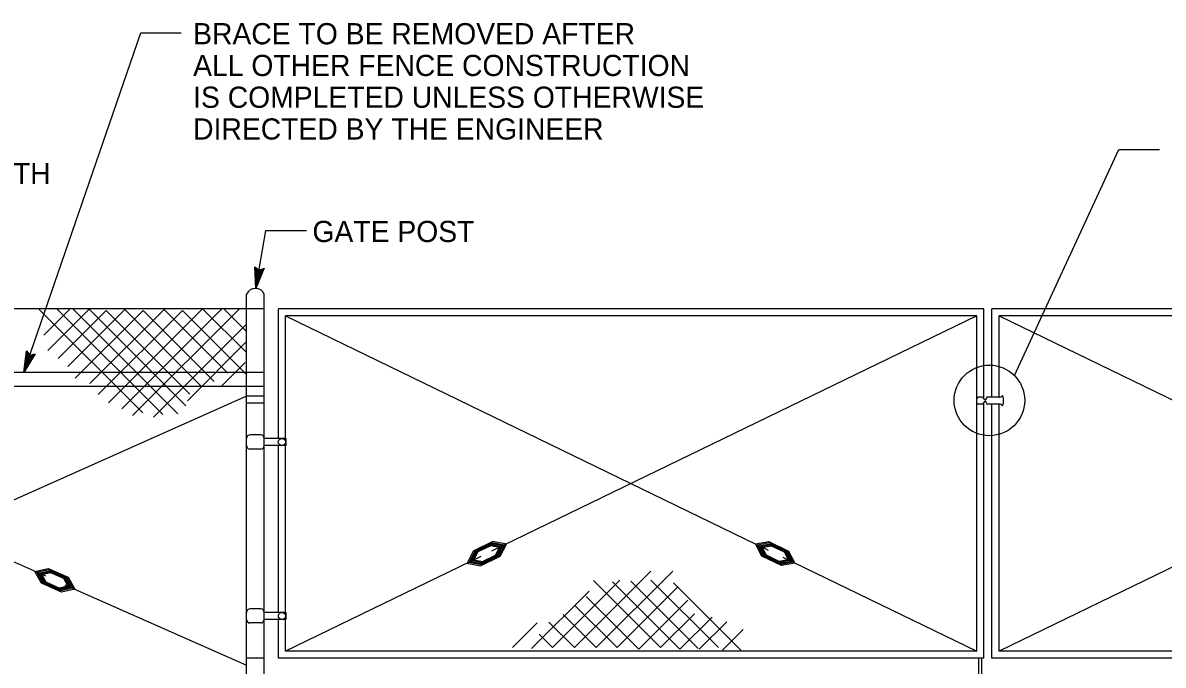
# Model space of a CAD drawing. Extents: x -121933 to -117742, y -103160 to -100084.
# Drawn here: x -121289.1 to -120965.9, y -102377.2 to -102195.2 of the extents above; entities that cross this region are included whole.
import ezdxf

# ---------------------------------------------------------------- set-up
doc = ezdxf.new("R2010")
doc.units = 0
for name, color, linetype in [('G-MARK', 7, 'Continuous'), ('Misc CnstDet(22)', 7, 'Continuous'), ('Nongeo Data(60)', 7, 'Continuous')]:
    doc.layers.add(name, color=color, linetype=linetype)

msp = doc.modelspace()

# ---------------------------------------------------------------- linework, layer by layer
at = {"layer": 'G-MARK'}
for p, q in [((-121255.73, -102197.99), (-121244.23, -102197.99)), ((-120978.4, -102231.09), (-120966.89, -102231.09)), ((-121220.22, -102254.04), (-121208.72, -102254.04)), ((-121223.06, -102270.41), (-121223.35, -102264.27)), ((-121223.35, -102264.27), (-121223.35, -102264.27)), ((-121223.35, -102264.27), (-121222.17, -102265.29)), ((-121220.72, -102264.73), (-121223.06, -102270.41)), ((-121222.83, -102269.04), (-121223.03, -102264.56)), ((-121221.1, -102264.88), (-121222.83, -102269.05)), ((-121222.59, -102267.69), (-121222.72, -102264.8)), ((-121221.5, -102265.05), (-121222.59, -102267.69)), ((-121222.35, -102266.33), (-121222.41, -102265.09)), ((-121221.87, -102265.16), (-121222.35, -102266.33)), ((-121222.17, -102265.29), (-121220.72, -102264.73)), ((-121220.72, -102264.73), (-121220.72, -102264.73)), ((-121223.06, -102270.41), (-121223.06, -102270.41)), ((-121288.84, -102294.24), (-121288.14, -102288.14)), ((-121285.62, -102289.01), (-121288.84, -102294.24)), ((-121288.39, -102292.93), (-121287.88, -102288.48)), ((-121286.02, -102289.09), (-121288.39, -102292.94)), ((-121288.14, -102288.14), (-121288.14, -102288.14)), ((-121288.14, -102288.14), (-121287.14, -102289.33)), ((-121287.94, -102291.63), (-121287.61, -102288.76)), ((-121286.44, -102289.2), (-121287.94, -102291.63)), ((-121287.49, -102290.33), (-121287.35, -102289.1)), ((-121286.83, -102289.25), (-121287.49, -102290.33)), ((-121287.14, -102289.33), (-121285.62, -102289.01)), ((-121285.62, -102289.01), (-121285.62, -102289.01)), ((-121288.84, -102294.24), (-121288.84, -102294.24))]:
    msp.add_line(p, q, dxfattribs=at)
for points in [[(-121288.84, -102294.24), (-121255.73, -102197.99), (-121255.73, -102197.99)], [(-121008.05, -102295.1), (-120978.4, -102231.09), (-120978.4, -102231.09)], [(-121223.06, -102270.41), (-121220.22, -102254.04)]]:
    msp.add_lwpolyline(points, dxfattribs=at)
msp.add_circle((-121015.12, -102302.17), 10, dxfattribs=at)
at = {"layer": 'Misc CnstDet(22)'}
msp.add_lwpolyline([(-121017.32, -102375.24), (-121017.32, -102390.2), (-121018.08, -102390.2), (-121018.08, -102375.24)], dxfattribs=at)
at = {"layer": 'Nongeo Data(60)'}
for p, q in [((-121225.7, -102358.97), (-121225.7, -102272.05)), ((-121220.7, -102358.97), (-121220.7, -102272.05)), ((-121220.7, -102276.24), (-121402.53, -102276.24)), ((-121255.16, -102305.72), (-121284.47, -102276.41)), ((-121283.17, -102283.65), (-121275.93, -102276.41)), ((-121282.1, -102288.04), (-121270.23, -102276.17)), ((-121249.46, -102306.2), (-121279.49, -102276.17)), ((-121279.13, -102290.29), (-121265.48, -102276.65)), ((-121276.4, -102292.55), (-121260.26, -102276.41)), ((-121245.19, -102305.96), (-121274.98, -102276.17)), ((-121274.27, -102295.87), (-121255.04, -102276.65)), ((-121242.94, -102303.7), (-121270.47, -102276.17)), ((-121270.11, -102297.41), (-121249.11, -102276.41)), ((-121267.74, -102300.5), (-121243.89, -102276.65)), ((-121241.75, -102300.38), (-121265.48, -102276.65)), ((-121264.89, -102302.87), (-121238.19, -102276.17)), ((-121261.07, -102304.51), (-121232.74, -102276.18)), ((-121238.55, -102298.13), (-121260.26, -102276.41)), ((-121258.01, -102306.43), (-121227.75, -102276.17)), ((-121234.87, -102296.82), (-121255.04, -102276.65)), ((-121231.07, -102294.45), (-121249.11, -102276.41)), ((-121225.73, -102294.8), (-121243.89, -102276.65)), ((-121225.73, -102288.63), (-121238.19, -102276.17)), ((-121225.93, -102282.47), (-121232.33, -102276.07)), ((-121216.7, -102312.97), (-121216.7, -102276.24)), ((-121016.7, -102276.24), (-121216.7, -102276.24)), ((-121016.7, -102301.58), (-121016.7, -102276.24)), ((-120814.39, -102276.24), (-121014.39, -102276.24)), ((-121014.39, -102301.21), (-121014.39, -102276.24)), ((-121214.7, -102312.95), (-121214.7, -102278.24)), ((-121214.7, -102278.24), (-121077.83, -102344.59)), ((-121018.7, -102278.24), (-121214.7, -102278.24)), ((-121018.7, -102278.24), (-121156.27, -102344.92)), ((-121018.7, -102301.21), (-121018.7, -102278.24)), ((-120816.39, -102278.24), (-121012.39, -102278.24)), ((-121012.39, -102278.24), (-120875.51, -102344.59)), ((-121012.39, -102301.24), (-121012.39, -102278.24)), ((-121252.08, -102306.91), (-121225.94, -102280.78)), ((-121242.46, -102302.28), (-121225.69, -102285.51)), ((-121232.85, -102298.13), (-121226.14, -102291.41)), ((-121220.7, -102294.24), (-121402.7, -102294.24)), ((-121220.7, -102298.24), (-121402.7, -102298.24)), ((-121397.3, -102300.95), (-121282.76, -102351.93)), ((-121225.7, -102300.95), (-121341.65, -102352.55)), ((-121220.7, -102300.95), (-121225.7, -102300.95)), ((-121018.7, -102373.24), (-121018.7, -102301.21)), ((-121017.13, -102301.24), (-121018.28, -102301.24)), ((-121016.7, -102301.59), (-121016.7, -102301.58)), ((-121012.39, -102301.24), (-121015.78, -102301.24)), ((-121014.39, -102301.24), (-121014.39, -102301.21)), ((-121220.7, -102302.95), (-121225.7, -102302.95)), ((-121017.13, -102303.24), (-121018.28, -102303.24)), ((-121016.7, -102375.24), (-121016.7, -102302.9)), ((-121012.39, -102303.24), (-121015.74, -102303.24)), ((-121014.39, -102375.24), (-121014.39, -102303.24)), ((-121012.39, -102373.24), (-121012.39, -102303.24)), ((-121225.7, -102311.94), (-121225.7, -102309.67)), ((-121225.7, -102317.59), (-121225.7, -102311.9)), ((-121221.7, -102311.95), (-121224.7, -102311.95)), ((-121220.7, -102311.93), (-121220.7, -102309.67)), ((-121220.7, -102317.59), (-121220.7, -102311.93)), ((-121216.7, -102312.95), (-121216.7, -102309.67)), ((-121225.7, -102314.95), (-121225.7, -102312.95)), ((-121214.58, -102312.95), (-121220.7, -102312.95)), ((-121220.7, -102314.95), (-121220.7, -102312.95)), ((-121214.58, -102314.95), (-121220.7, -102314.95)), ((-121216.7, -102358.97), (-121216.7, -102314.81)), ((-121216.7, -102317.59), (-121216.7, -102314.95)), ((-121214.7, -102362.24), (-121214.7, -102314.95)), ((-121221.7, -102315.95), (-121224.7, -102315.95)), ((-121155.86, -102342.16), (-121161.43, -102344.87)), ((-121156.04, -102342.51), (-121161.05, -102344.94)), ((-121156.2, -102342.82), (-121160.71, -102345.01)), ((-121156.34, -102343.09), (-121160.41, -102345.07)), ((-121156.47, -102343.35), (-121160.13, -102345.12)), ((-121153.98, -102343.82), (-121156.47, -102343.35)), ((-121153.57, -102343.62), (-121156.34, -102343.09)), ((-121153.12, -102343.4), (-121156.2, -102342.82)), ((-121152.62, -102343.16), (-121156.04, -102342.51)), ((-121152.06, -102342.89), (-121155.86, -102342.16)), ((-121155.15, -102346.07), (-121153.98, -102343.82)), ((-121154.87, -102346.12), (-121153.57, -102343.62)), ((-121154.56, -102346.18), (-121153.12, -102343.4)), ((-121154.22, -102346.25), (-121152.62, -102343.16)), ((-121153.84, -102346.32), (-121152.06, -102342.89)), ((-121081.42, -102342.86), (-121077.62, -102342.13)), ((-121079.64, -102346.29), (-121081.42, -102342.86)), ((-121080.86, -102343.14), (-121077.45, -102342.48)), ((-121079.26, -102346.23), (-121080.86, -102343.14)), ((-121080.36, -102343.38), (-121077.28, -102342.8)), ((-121078.92, -102346.17), (-121080.36, -102343.38)), ((-121079.91, -102343.61), (-121077.14, -102343.08)), ((-121078.61, -102346.11), (-121079.91, -102343.61)), ((-121079.5, -102343.81), (-121077.01, -102343.34)), ((-121078.34, -102346.06), (-121079.5, -102343.81)), ((-121077.62, -102342.13), (-121072.05, -102344.85)), ((-121077.45, -102342.48), (-121072.43, -102344.92)), ((-121077.28, -102342.8), (-121072.77, -102344.99)), ((-121077.14, -102343.08), (-121073.08, -102345.06)), ((-121077.01, -102343.34), (-121073.35, -102345.11)), ((-121159.29, -102346.39), (-121214.7, -102373.24)), ((-121161.43, -102344.87), (-121163.21, -102348.31)), ((-121161.05, -102344.94), (-121162.65, -102348.04)), ((-121160.71, -102345.01), (-121162.15, -102347.79)), ((-121162.15, -102347.79), (-121159.08, -102348.38)), ((-121160.41, -102345.07), (-121161.7, -102347.57)), ((-121161.7, -102347.57), (-121158.93, -102348.1)), ((-121160.13, -102345.12), (-121161.3, -102347.38)), ((-121161.3, -102347.38), (-121158.8, -102347.85)), ((-121159.41, -102349.03), (-121153.84, -102346.32)), ((-121159.23, -102348.69), (-121154.22, -102346.25)), ((-121159.08, -102348.38), (-121154.56, -102346.18)), ((-121158.93, -102348.1), (-121154.87, -102346.12)), ((-121158.8, -102347.85), (-121155.15, -102346.07)), ((-121074.07, -102349), (-121079.64, -102346.29)), ((-121074.25, -102348.66), (-121079.26, -102346.23)), ((-121074.41, -102348.36), (-121078.92, -102346.17)), ((-121074.55, -102348.09), (-121078.61, -102346.11)), ((-121074.68, -102347.84), (-121078.34, -102346.06)), ((-121072.19, -102347.37), (-121074.68, -102347.84)), ((-121071.78, -102347.56), (-121074.55, -102348.09)), ((-121071.33, -102347.78), (-121074.41, -102348.36)), ((-121073.66, -102346.61), (-121018.7, -102373.24)), ((-121073.35, -102345.11), (-121072.19, -102347.37)), ((-121073.08, -102345.06), (-121071.78, -102347.56)), ((-121072.77, -102344.99), (-121071.33, -102347.78)), ((-121072.43, -102344.92), (-121070.83, -102348.01)), ((-121072.05, -102344.85), (-121070.27, -102348.28)), ((-120956.97, -102346.39), (-121012.39, -102373.24)), ((-121285.74, -102350.62), (-121281.97, -102349.77)), ((-121283.85, -102353.99), (-121285.74, -102350.62)), ((-121285.18, -102350.88), (-121281.78, -102350.11)), ((-121283.47, -102353.91), (-121285.18, -102350.88)), ((-121284.66, -102351.11), (-121281.61, -102350.42)), ((-121283.13, -102353.84), (-121284.66, -102351.11)), ((-121284.2, -102351.31), (-121281.46, -102350.69)), ((-121283.79, -102351.5), (-121281.32, -102350.94)), ((-121281.97, -102349.77), (-121276.31, -102352.29)), ((-121281.78, -102350.11), (-121276.68, -102352.38)), ((-121281.61, -102350.42), (-121277.02, -102352.46)), ((-121281.46, -102350.69), (-121277.33, -102352.53)), ((-121281.32, -102350.94), (-121277.6, -102352.59)), ((-121163.21, -102348.31), (-121159.41, -102349.03)), ((-121162.65, -102348.04), (-121159.23, -102348.69)), ((-121132.78, -102372.23), (-121111.07, -102350.52)), ((-121126.61, -102372.23), (-121104.9, -102350.52)), ((-121070.83, -102348.01), (-121074.25, -102348.66)), ((-121070.27, -102348.28), (-121074.07, -102349)), ((-121282.83, -102353.77), (-121284.2, -102351.31)), ((-121278.19, -102356.52), (-121283.85, -102353.99)), ((-121282.55, -102353.71), (-121283.79, -102351.5)), ((-121278.38, -102356.18), (-121283.47, -102353.91)), ((-121278.54, -102355.88), (-121283.13, -102353.84)), ((-121278.7, -102355.61), (-121282.83, -102353.77)), ((-121278.84, -102355.36), (-121282.55, -102353.71)), ((-121277.6, -102352.59), (-121276.36, -102354.8)), ((-121277.33, -102352.53), (-121275.95, -102354.99)), ((-121277.23, -102354.39), (-121225.69, -102377.17)), ((-121277.02, -102352.46), (-121275.49, -102355.19)), ((-121276.68, -102352.38), (-121274.98, -102355.42)), ((-121276.31, -102352.29), (-121274.42, -102355.67)), ((-121138.95, -102372.23), (-121119.85, -102353.13)), ((-121108.34, -102372.23), (-121127.32, -102353.25)), ((-121102.88, -102372.71), (-121121.98, -102353.6)), ((-121097.66, -102372.47), (-121116.76, -102353.36)), ((-121091.96, -102372.23), (-121111.07, -102353.13)), ((-121085.55, -102372.94), (-121104.66, -102353.84)), ((-121276.36, -102354.8), (-121278.84, -102355.36)), ((-121275.95, -102354.99), (-121278.7, -102355.61)), ((-121275.49, -102355.19), (-121278.54, -102355.88)), ((-121274.98, -102355.42), (-121278.38, -102356.18)), ((-121274.42, -102355.67), (-121278.19, -102356.52)), ((-121144.89, -102372.47), (-121128.63, -102356.21)), ((-121120.68, -102372.23), (-121103.35, -102354.91)), ((-121225.7, -102361.24), (-121225.7, -102358.97)), ((-121225.7, -102366.89), (-121225.7, -102358.97)), ((-121220.7, -102361.22), (-121220.7, -102358.97)), ((-121220.7, -102366.89), (-121220.7, -102358.97)), ((-121216.7, -102362.24), (-121216.7, -102358.97)), ((-121216.7, -102362.19), (-121216.7, -102358.97)), ((-121120.68, -102372.23), (-121132.66, -102360.25)), ((-121114.51, -102372.71), (-121129.46, -102357.76)), ((-121114.51, -102372.71), (-121100.62, -102358.82)), ((-121225.7, -102366.89), (-121225.7, -102361.19)), ((-121225.7, -102364.24), (-121225.7, -102362.24)), ((-121221.7, -102361.24), (-121224.7, -102361.24)), ((-121220.7, -102366.89), (-121220.7, -102361.22)), ((-121220.7, -102364.24), (-121220.7, -102362.24)), ((-121214.58, -102362.24), (-121220.59, -102362.24)), ((-121126.61, -102372.23), (-121135.99, -102362.86)), ((-121108.34, -102372.23), (-121098.72, -102362.62)), ((-121102.88, -102372.71), (-121093.74, -102363.57)), ((-121225.7, -102426.24), (-121225.7, -102366.89)), ((-121221.7, -102365.24), (-121224.7, -102365.24)), ((-121214.58, -102364.24), (-121220.7, -102364.24)), ((-121220.7, -102426.24), (-121220.7, -102366.89)), ((-121216.7, -102366.89), (-121216.7, -102364.24)), ((-121216.7, -102375.24), (-121216.7, -102366.89)), ((-121214.7, -102366.89), (-121214.7, -102364.24)), ((-121214.7, -102366.89), (-121214.7, -102364.24)), ((-121214.7, -102373.24), (-121214.7, -102366.89)), ((-121150.34, -102372.23), (-121143.34, -102365.23)), ((-121132.78, -102372.23), (-121140.02, -102364.99)), ((-121097.42, -102372.71), (-121089.59, -102364.88)), ((-121090.77, -102372.94), (-121084.96, -102367.13)), ((-121138.95, -102372.23), (-121142.75, -102368.44)), ((-121018.7, -102373.24), (-121214.7, -102373.24)), ((-120816.39, -102373.24), (-121012.39, -102373.24)), ((-121220.7, -102375.24), (-121225.7, -102375.24)), ((-121016.7, -102375.24), (-121216.7, -102375.24)), ((-120814.39, -102375.24), (-121014.39, -102375.24))]:
    msp.add_line(p, q, dxfattribs=at)
for centre in [(-121215.71, -102313.95), (-121215.7, -102363.24)]:
    msp.add_circle(centre, 1, dxfattribs=at)
for centre, radius, start, end in [((-121223.2, -102273.13), 2.72, 23.2888, 156.7112), ((-121018.26, -102301.69), 0.45, 90.9719, 166.9649), ((-121017.14, -102301.69), 0.45, 13.0351, 89.0281), ((-121016.34, -102301.61), 0.368, 177.9728, 273.0727), ((-121016.34, -102302.88), 0.368, 86.9273, 182.0272), ((-121016.53, -102301.46), 0.552, 292.64, 356.8611), ((-121016.53, -102303.02), 0.552, 3.1389, 67.36), ((-121015.76, -102301.47), 0.223, 82.9178, 185.5923), ((-121012.31, -102300.06), 1.18, 266.4373, 320.9406), ((-121014.68, -102302.25), 3.59, 336.5119, 23.6238), ((-121018.27, -102302.79), 0.45, 193.0351, 269.0281), ((-121017.14, -102302.79), 0.45, 270.9719, 346.9649), ((-121015.76, -102303.02), 0.223, 174.4077, 277.0822), ((-121012.31, -102304.43), 1.18, 39.0594, 93.5627), ((-121224.7, -102312.95), 1, 90, 180), ((-121221.7, -102312.95), 1, 0, 90), ((-121224.7, -102314.95), 1, 180, 270), ((-121221.7, -102314.95), 1, 270, 0), ((-121224.7, -102362.24), 1, 90, 180), ((-121221.7, -102362.24), 1, 0, 90), ((-121224.7, -102364.24), 1, 180, 270), ((-121221.7, -102364.24), 1, 270, 0)]:
    msp.add_arc(centre, radius, start, end, dxfattribs=at)
for centre in [(-121214.58, -102313.95), (-121214.58, -102363.24)]:
    msp.add_ellipse(centre, major_axis=(0, -1), ratio=0.098201, start_param=0, end_param=3.141593, dxfattribs=at)

# ---------------------------------------------------------------- texts
at = {"layer": 'Misc CnstDet(22)'}
for s, p in [('BRACE TO BE REMOVED AFTER', (-121240.86, -102201.24)), ('ALL OTHER FENCE CONSTRUCTION', (-121240.86, -102210.24)), ('IS COMPLETED UNLESS OTHERWISE', (-121240.86, -102219.24)), ('DIRECTED BY THE ENGINEER', (-121240.86, -102228.24)), ('HORIZONTAL BRACE WITH', (-121385.57, -102240.86)), ('GATE POST', (-121207.04, -102257.29))]:
    msp.add_text(s, height=6, dxfattribs=at).set_placement(p)

doc.saveas('drawing.dxf')
